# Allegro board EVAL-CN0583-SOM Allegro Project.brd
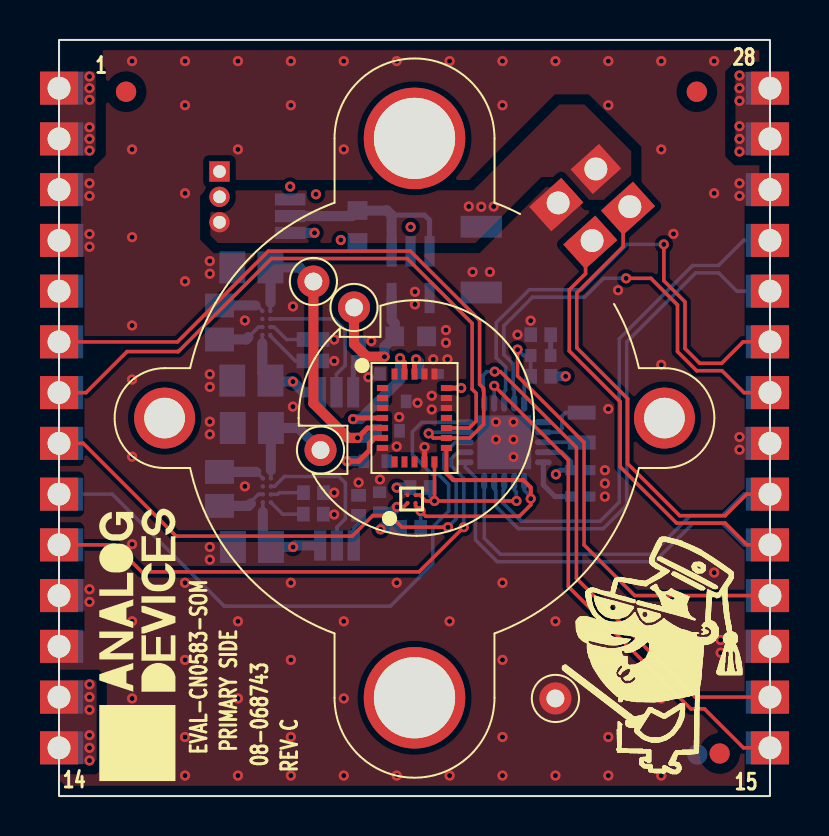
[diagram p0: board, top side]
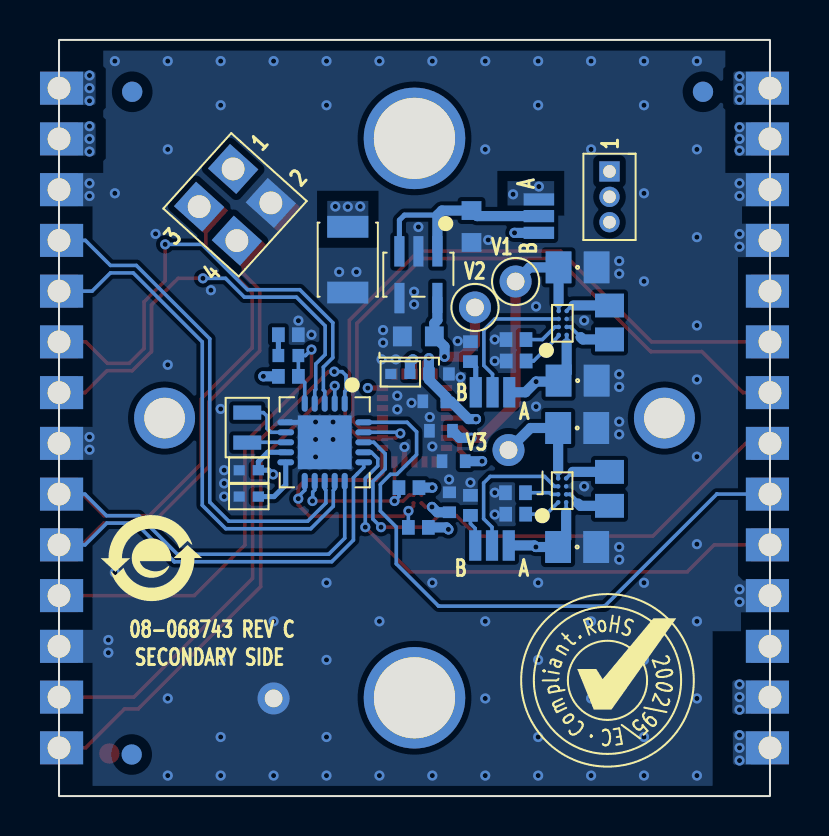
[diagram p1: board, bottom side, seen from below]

Outline 35.56 x 37.85 mm; copper layers: TOP, L2_GND, L3_VCC, BOTTOM. Coordinates in mm from the lower left corner of the outline.
Outline path: rectangle 0,0 35.56,37.85

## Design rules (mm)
constraint set DEFAULT: min track width 0.178

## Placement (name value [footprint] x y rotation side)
C1  0.1uF  [C0402]  24.09 22.05 0 bottom
C2  1uF  [C0402H22]  26.07 16.31 0 bottom
C3  1uF  [C0402H22]  26.07 14.99 0 bottom
C4  0.1uF  [C0402]  16.03 14.71 90 bottom
C5  10UF  [C0402H32]  16.79 19.76 0 bottom
C6  0.1uF  [C0402]  16.56 21.13 180 bottom
C7  10UF  [C0402H32]  16.46 18.28 0 bottom
C8  10UF  [C0402H32]  15.82 16.76 0 bottom
C9  1uF  [C0402H22]  18.49 21.13 0 bottom
C10  100uF  [C1210H106]  21.12 26.85 270 bottom
C11  22uF  [C0805H60]  9.62 20.79 180 bottom
C12  22uF  [C0805H60]  9.62 26.46 180 bottom
C13  22uF  [C0805H60]  9.65 12.47 180 bottom
C14  22uF  [C0805H60]  9.64 18.42 180 bottom
C15  2.2uF  [C0603]  14.93 28.51 270 bottom
C16  2.2uF  [C0603]  17.59 23.01 0 bottom
GND  TP_VIA  [TPC63D35]  24.83 4.89 0 top
JP1  M50-3530342  [CNTHMHDR1X3L150W83H169]  8.03 31.26 270 bottom
JP2  3PIN_SOLDER_JUMPER  [JPRSLD03]  13.88 20.21 0 bottom
JP3  3PIN_SOLDER_JUMPER  [JPRSLD03]  13.9 12.54 0 bottom
JP4  3PIN_SOLDER_JUMPER  [JPRSLD03]  11.56 29.03 270 bottom
L1  2.2UH  [L0805]  8.03 23.7 90 bottom
L2  2.2UH  [L0805]  8.03 15.38 90 bottom
NOREF  -  []  35.56 0 90 top
NOREF#2  -  [unnamed#2]  17.78 4.92 0 top
NOREF#3  -  []  0 37.85 0 top
NOREF#4  -  []  -81.28 185.29 0 top
NOREF#5  -  [unnamed#2]  3.35 35.26 0 top
NOREF#6  -  []  6.02 -64.44 0 top
NOREF#7  -  []  0 0 0 top
NOREF#8  -  []  -119.38 -141.1 0 top
NOREF#9  -  []  -119.38 -141.1 0 top
NOREF#10  -  []  5.28 18.92 0 top
NOREF#11  -  []  5.28 18.92 0 top
NOREF#12  -  []  35.56 35.43 0 top
NOREF#13  -  [unnamed#2]  30.28 18.92 0 top
NOREF#14  -  [unnamed#2]  33.04 2.13 0 top
NOREF#15  -  []  35.56 0 90 top
NOREF#16  -  []  17.78 18.92 0 top
NOREF#17  -  []  0 0 0 top
NOREF#18  -  []  35.56 37.85 180 top
NOREF#19  -  []  3.92 7.45 90 top
NOREF#20  -  [unnamed#2]  17.78 32.92 0 top
NOREF#21  -  []  0 0 0 top
NOREF#22  -  []  0 37.85 0 top
NOREF#23  -  []  -68.58 1.14 0 top
NOREF#24  -  []  -61.34 232.28 0 top
NOREF#25  -  [unnamed#2]  5.28 18.92 0 top
NOREF#26  -  [unnamed#2]  31.9 35.26 0 top
NOREF#27  -  []  0 37.85 270 top
NOREF#28  -  []  35.56 0 0 top
NOREF#29  -  []  -119.38 -141.1 0 top
NOREF#30  -  []  -119.38 -141.1 0 top
NOREF#31  -  []  260.53 309.63 0 top
NOREF#32  -  []  5.28 18.92 0 top
NOREF#33  -  [unnamed#2]  3.35 35.25 180 bottom
NOREF#34  -  [unnamed#2]  31.93 2.08 180 bottom
NOREF#35  -  []  19.5 31.16 180 bottom
NOREF#36  -  []  -17.78 5.16 180 bottom
NOREF#37  -  [unnamed#2]  31.9 35.25 180 bottom
P1  TSW-102-08-T-D  [CNSAMTEC2X2H338LD36]  26.85 31.39 312 bottom
P2-A  TSW-114-16-G-S  [CNHDR1X14H420]  0 35.43 270 top
P2-B  TSW-114-16-G-S  [CNHDR1X14H420]  35.56 35.43 270 top
R1  10K  [R0402]  24.09 21.01 180 bottom
R2  10  [R0402]  24.09 23.09 180 bottom
R3  10K  [R0402]  18.06 15.44 0 bottom
R4  10K  [R0402]  17.59 13.45 0 bottom
R5  10K  [R0402]  14.98 22.25 90 bottom
R6  324K  [R0402]  12.69 21.78 0 bottom
R7  324K  [R0402]  12.7 22.85 0 bottom
R8  10K  [R0402]  14.98 14.55 90 bottom
R9  40.2K  [R0402]  12.72 14.11 0 bottom
R10  324K  [R0402]  12.73 15.18 0 bottom
U1  MAX32660GTP+  [QFN20_4X4_PAD2_7X2_7]  22.27 17.71 0 bottom
U2  MAX31875R0TZS+T  [WLCSP4H15]  17.63 14.87 0 top
U3  ADPD188BI-ACEZ  [LGA24_A]  17.78 18.92 270 top
U4  MAX77837EWA+T  [WLP8_W81E1_1]  10.37 23.68 90 bottom
U5  MAX77837EWA+T  [WLP8_W81E1_1]  10.39 15.3 90 bottom
U6  ADP162AUJZ-1.8  [TSOT-5]  17.59 26.1 0 bottom
VDD  TP_VIA  [TPC63D35]  14.75 24.46 0 top
VLED1  TP_VIA  [TPC63D35]  12.72 25.76 0 top
VLED3  TP_VIA  [TPC63D35]  13.08 17.32 0 top
Y1  32.768KHZ  [YSML79W47H24]  26.15 18.44 270 bottom

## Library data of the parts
C1 C4 C6 = CAP: User Part Number: UPN; Tolerance: 10; alternate symbols: (C0402); part number: CAP_SM-0.1UF,16V,10,E033898,C0402; tolerance: 10
C2 C3 C9 = CAP: Tolerance: 10; User Part Number: UPN; alternate symbols: (C0402H22); part number: CAP_SM-1UF,25V,10,E033656,C0402H22; tolerance: 10
C5 C7 C8 = CAP: User Part Number: UPN; Tolerance: 20; alternate symbols: (C0402H32); part number: CAP_SM-10UF,10V,20,E057793,C0402H32; tolerance: 20
C10 = CAP: Tolerance: 20; User Part Number: UPN; alternate symbols: (C1210H106); part number: CAP_SM-100UF,10V,20,E033226,C1210H106; tolerance: 20
C11-C14 = CAP: Tolerance: 20; User Part Number: UPN; alternate symbols: (C0805H60); part number: CAP_SM-22UF,25V,20,E032575,C0805H60; tolerance: 20
C15 C16 = CAP: User Part Number: UPN; Tolerance: 10; alternate symbols: (C0603); part number: CAP_SM-2.2UF,25V,10,E031885,C0603; tolerance: 10
GND VDD VLED1 VLED3 = NCTESTPAD: Tolerance: N/A; User Part Number: UPN; alternate symbols: (TPC63D35); part number: NCTESTPAD_TH-TP_VIA,E012149,TPC63D35; tolerance: N/A
JP1 = CN3P: Tolerance: N/A; User Part Number: UPN; alternate symbols: (CNTHMHDR1X3L150W83H169); part number: CN3P_TH-M50-3530342,E055467,CNTHMHDR1X3L150W83H169; tolerance: N/A
JP2-JP4 = NC3P_JMPR: Tolerance: N/A; User Part Number: UPN; alternate symbols: (JPRSLD03); part number: NC3P_JMPR_SM-3PIN_SOLDER_JUMPER,E005606,JPRSLD03; tolerance: N/A
L1 L2 = IND: User Part Number: UPN; Tolerance: 20; alternate symbols: (L0805); part number: IND_SM-2.2UH,20,E033261,L0805; tolerance: 20
P1 = CN4P: User Part Number: UPN; Tolerance: N/A; alternate symbols: (CNSAMTEC2X2H338LD36); part number: CN4P_TH-TSW-102-08-T-D,E031363,CNSAMTEC2X2H338LD36; tolerance: N/A
P2-A P2-B = CN14P: User Part Number: UPN; Tolerance: N/A; alternate symbols: (CNHDR1X14H420); part number: CN14P_TH-TSW-114-16-G-S,E017083,CNHDR1X14H420; tolerance: N/A
R1 R3-R5 R8 = RES: User Part Number: UPN; Tolerance: 1; alternate symbols: (R0402); part number: RES_SM-10K,E003751,1/10W,1,R0402; tolerance: 1
R2 = RES: User Part Number: UPN; Tolerance: 1; alternate symbols: (R0402); part number: RES_SM-10,E003768,1/10W,1,R0402; tolerance: 1
R6 R7 R10 = RES: User Part Number: UPN; Tolerance: 1; alternate symbols: (R0402); part number: RES_SM-324K,E026129,1/10W,1,R0402; tolerance: 1
R9 = RES: User Part Number: UPN; Tolerance: 1; alternate symbols: (R0402); part number: RES_SM-40.2K,E006353,1/10W,1,R0402; tolerance: 1
U1 = ICMAX32660: User Part Number: UPN; Tolerance: N/A; alternate symbols: (QFN20_4X4_PAD2_7X2_7); part number: ICMAX32660_SM-MAX32660GTP+,E047371,QFN20_4X4_PAD2_7X2_7; tolerance: N/A
U2 = ICMAX31875: Tolerance: N/A; User Part Number: UPN; alternate symbols: (WLCSP4H15); part number: ICMAX31875_SM-MAX31875R0TZS+T,E054242,WLCSP4H15; tolerance: N/A
U3 = ADPD188BI: Tolerance: N/A; User Part Number: UPN; alternate symbols: (LGA24_A); part number: ADPD188BI_SM-ADPD188BI-ACEZ,E032759,LGA24_A; tolerance: N/A
U4 U5 = ADMAX77837: Tolerance: N/A; User Part Number: UPN; alternate symbols: (WLP8_W81E1_1); part number: ADMAX77837_SM-MAX77837EWA+T,E060730,WLP8_W81E1_1; tolerance: N/A
U6 = ADP16X_V3: User Part Number: UPN; Tolerance: N/A; alternate symbols: (TSOT-5); part number: ADP16X_V3_SM-ADP162AUJZ-1.8,E024079,TSOT-5; tolerance: N/A
Y1 = XTAL: User Part Number: UPN; Tolerance: 20ppm; alternate symbols: (YSML79W47H24); part number: XTAL_SM-32.768KHZ,E047370,YSML79W47H24; tolerance: 20ppm

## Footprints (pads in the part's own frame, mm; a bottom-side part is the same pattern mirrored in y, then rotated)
C0402
  rect 0.584x0.66 smd: 1(-0.5,0) 2(0.5,0)
C0402H22
  rect 0.559x0.508 smd: 1(-0.479,0) 2(0.479,0)
C0402H32
  rect 0.533x0.686 smd: 1(-0.577,0) 2(0.577,0)
C0603
  rect 0.94x0.991 smd: 1(-0.8,0) 2(0.8,0)
C0805H60
  rect 1.295x1.6 smd: 1(-0.953,0) 2(0.953,0)
C1210H106
  rect 1.092x2.057 smd: 1(-1.646,0) 2(1.646,0)
CNHDR1X14H420
  rect 1.651x1.905 hole 1.143: 1(0,0) 2(2.54,0) 3(5.08,0) 4(7.62,0) 5(10.16,0) 6(12.7,0) 7(15.24,0) 8(17.78,0) 9(20.32,0) 10(22.86,0) 11(25.4,0) 12(27.94,0) 13(30.48,0) 14(33.02,0)
CNSAMTEC2X2H338LD36
  rect 1.651x1.905 hole 1.143: 1(0,0)
  rect 1.651x2.159 hole 1.143: 2(0,2.54) 3(2.54,0) 4(2.54,2.54)
CNTHMHDR1X3L150W83H169
  rect 1.016x1.016 hole 0.635: 1(0,0)
  round 1.016 hole 0.635: 2(1.27,0) 3(2.54,0)
JPRSLD03
  rect 0.61x1.524 smd: 1(-0.838,0) 2(0,0) 3(0.838,0)
L0805
  rect 1.194x1.448 smd: 1(-0.85,0) 2(0.85,0)
LGA24_A
  rect 0.305x0.559 smd: 1(-1.5,-1.6) 2(-1,-1.6) 3(-0.5,-1.6) 4(0,-1.6) 5(0.5,-1.6) 6(1,-1.6) 7(1.5,-1.6) 13(1.5,1.6) 14(1,1.6) 15(0.5,1.6) 16(0,1.6) 17(-0.5,1.6) 18(-1,1.6) 19(-1.5,1.6)
  rect 0.559x0.305 smd: 8(2.2,-1) 9(2.2,-0.5) 10(2.2,0) 11(2.2,0.5) 12(2.2,1) 20(-2.2,1) 21(-2.2,0.5) 22(-2.2,0) 23(-2.2,-0.5) 24(-2.2,-1)
QFN20_4X4_PAD2_7X2_7
  oval 0.305x0.838 smd: 1(-1,-1.95) 2(-0.5,-1.95) 3(0,-1.95) 4(0.5,-1.95) 5(1,-1.95) 11(1,1.95) 12(0.5,1.95) 13(0,1.95) 14(-0.5,1.95) 15(-1,1.95)
  oval 0.838x0.305 smd: 6(1.95,-1) 7(1.95,-0.5) 8(1.95,0) 9(1.95,0.5) 10(1.95,1) 16(-1.95,1) 17(-1.95,0.5) 18(-1.95,0) 19(-1.95,-0.5) 20(-1.95,-1)
  rect 2.692x2.692 smd: PAD(0,0)
R0402
  rect 0.635x0.737 smd: 1(-0.5,0) 2(0.5,0)
TPC63D35
  round 1.6 hole 0.889: 1(0,0)
TSOT-5
  rect 0.508x1.524 smd: 1(-0.95,-1.17) 2(0,-1.17) 3(0.95,-1.17) 4(0.95,1.17) 5(-0.95,1.17)
unnamed#2
  round 5.08 hole 4.064 unplated: (0,0)
WLCSP4H15
  round 0.203 smd: A1(-0.2,-0.2) A2(-0.2,0.2) B1(0.2,-0.2) B2(0.2,0.2)
WLP8_W81E1_1
  round 0.229 smd: A1(-0.6,0.2) A2(-0.2,0.2) A3(0.2,0.2) A4(0.6,0.2) B1(-0.6,-0.2) B2(-0.2,-0.2) B3(0.2,-0.2) B4(0.6,-0.2)
YSML79W47H24
  rect 0.711x1.397 smd: 1(-0.75,0) 2(0.75,0)

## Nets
1V8_POWER: C2.1 C4.1 C5.1 C6.1 C16.1 R1.1 R3.1 R4.1 U1.9 U2.A1(VDD) U3.4 U3.19 U3.23 U6.5(VOUT) VDD.1(N1)
3V3_POWER: C8.1 C14.1 JP4.3 U3.6 U5.A4 VLED3.1(N1)
5V_POWER: C7.1 C12.1 U3.5 U4.A4 VLED1.1(N1)
GND: C2.2(N2) C3.2(N2) C4.2(N2) C5.2(N2) C6.2(N2) C7.2(N2) C8.2(N2) C9.2(N2) C10.2(N2) C11.2(N2) C12.2(N2) C13.2(N2) C14.2(N2) C15.2(N2) C16.2(N2) GND.1(N1) P1.2 P2-A.3 P2-A.4 P2-A.11 P2-A.12 P2-B.3 P2-B.8 P2-B.12 R2.2(N2) R5.2(N2) R6.2(N2) R7.2(N2) R8.2(N2) R9.2(N2) R10.2(N2) U1.6(VSS) U1.PAD U2.A2 U3.3 U3.7 U3.11 U3.17 U3.18 U3.20 U3.21 U4.B3 U5.B3 U6.2 U6.4
VBATT: JP1.1 JP4.1 P2-A.1 P2-A.2 P2-A.13 P2-A.14 P2-B.1 P2-B.2
ADPD_GPIO0: P2-A.6 U1.19 U3.14
ADPD_GPIO1: P2-A.7 U3.15
ALARM_OUT: P2-A.10 U1.17
BUTTON_IN: P2-A.9(N9) U1.20
EXT_VCC: C10.1 JP1.3(N3) P1.1
I2C_SCL: R3.2(N2) U1.12 U2.B2 U3.12
I2C_SDA: R4.2(N2) U1.11 U2.B1 U3.13
LED_OUT: P2-A.8 U1.18
RESET: C1.1 P2-B.11 R1.2(N2) U1.5
SPI_CS: P2-B.6 U1.3
SPI_MISO: P2-B.5 U1.14
SPI_MOSI: P2-B.4 U1.13
SPI_SCLK: P2-B.7 U1.4
SWDCLK: P2-B.13 U1.1
SWDIO: P2-B.14 U1.2
UART_RX: P1.3 P2-B.9(N9) U1.15
UART_TX: P1.4(N4) P2-B.10 U1.16
UNNAMED_10_ADPD188BI_I1_VREF: C9.1 U3.22(VREF)
UNNAMED_10_CAP_I73_N1: C3.1 U1.10
UNNAMED_10_CAP_I108_N2: C1.2(N2) R2.1
UNNAMED_10_ICMAX32660_I65_32KIN: U1.8 Y1.2(N2)
UNNAMED_10_ICMAX32660_I65_32KOUT: U1.7 Y1.1
UNNAMED_11_ADMAX77837_I143_EN: JP2.2(COM) U4.A3
UNNAMED_11_ADMAX77837_I143_IN: C11.1 C13.1 JP1.2 JP2.1 JP3.1 U4.B1 U5.B1
UNNAMED_11_ADMAX77837_I143_LX1: L1.1 U4.B2
UNNAMED_11_ADMAX77837_I143_LX2: L1.2(N2) U4.B4
UNNAMED_11_ADMAX77837_I143_SEL1: R6.1 U4.A1
UNNAMED_11_ADMAX77837_I143_SEL2: R7.1 U4.A2(SEL2)
UNNAMED_11_ADMAX77837_I144_EN: JP3.2(COM) U5.A3
UNNAMED_11_ADMAX77837_I144_LX1: L2.1 U5.B2
UNNAMED_11_ADMAX77837_I144_LX2: L2.2(N2) U5.B4
UNNAMED_11_ADMAX77837_I144_SEL1: R9.1 U5.A1
UNNAMED_11_ADMAX77837_I144_SEL2: R10.1 U5.A2(SEL2)
UNNAMED_11_ADP16XV3_I139_EN: C15.1 JP4.2(COM) U6.1 U6.3
UNNAMED_11_NC3PJMPR_I151_B: JP3.3 R8.1
UNNAMED_11_NC3PJMPR_I155_B: JP2.3 R5.1

Pads without a net: P2-A 5; U3 1 2 8 9 10 16 24

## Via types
v1: diameter 0.508, hole 0.254, TOP to BOTTOM, 173 vias

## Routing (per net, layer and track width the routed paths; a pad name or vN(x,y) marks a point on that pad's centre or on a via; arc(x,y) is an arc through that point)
1V8_POWER: length 21.2
  TOP w0.178: U2.A1 17.24,14.47 16.92,14.47 16.91,14.47 v1(16.91,14.47)
  TOP w0.254: U3.23 17.28,21.69 v1(17.06,21.92) ; U3.4 14.76,18.92 v1(14.7,18.87) ; v1(20.12,20.42) U3.19
  TOP w0.508: VDD.1 14.75,22.63 15.39,21.99 v1(16.28,21.99)
  BOTTOM w0.254: U1.9 25.12,17.21 25.59,16.74 C2.1 25.06,16.31 v1(24.85,16.1)
  BOTTOM w0.508: v1(14.7,18.87) 15.08,18.87 15.97,19.76 C5.1 16.21,19.99 17.06,20.84 C6.1 v1(17.06,21.92) ; R3.1 v1(16.89,15.44) ; R4.1 16.18,13.45 v1(16.08,13.35) ; C4.1 16.64,14.2 v1(16.91,14.47) ; v1(16.28,21.99) 16.28,22.5 C16.1 16.79,23.67 16.64,23.82 U6.5 ; R1.1 v1(25.34,21.01)
3V3_POWER: length 10
  TOP w0.254: v1(14.4,16.76) 14.98,16.76 15.52,17.3 15.52,17.65 15.79,17.92 U3.6
  BOTTOM w0.178: 10.59,16.31 U5.A4
  BOTTOM w0.508: C8.1 v1(14.4,16.76) ; JP4.3 v1(12.78,28.19) ; 10.59,16.31 C14.1 11.98,18.42 VLED3.1
5V_POWER: length 16.2
  TOP w0.254: v1(14.93,17.93) 15.43,18.42 U3.5
  TOP w0.508: v1(14.93,17.93) 14.45,17.93 12.72,19.66 VLED1.1
  BOTTOM w0.178: U4.A4 10.57,24.69 10.58,24.69
  BOTTOM w0.508: C7.1 15.52,17.93 v1(14.93,17.93) ; VLED1.1 12.02,26.46 C12.1 10.58,24.69
GND: length 2.3
  TOP w0.254: U3.11 v1(18.28,17.47) 18.28,17.49
  BOTTOM w0.254: U1.6 22.74,18.71 v1(22.73,18.72)
  vias: v1(1.52,30.67) v1(1.52,30.04) v1(1.52,28.13) v1(1.52,27.5) v1(1.52,10.35) v1(1.52,9.72) v1(3.66,36.79) v1(3.66,32.37) v1(3.66,27.97) v1(3.66,23.55) v1(3.66,20.85) v1(3.66,16.99) v1(3.66,12.61) v1(3.66,8.75) v1(3.66,4.89) v1(3.66,1.02) v1(6.3,36.79) v1(6.3,34.58) v1(6.3,30.17) v1(6.3,25.76) v1(6.3,10.68) v1(6.3,6.82) v1(6.3,2.96) v1(6.3,1.02) v1(7.54,26.78) v1(7.54,26.15) v1(7.54,21.11) v1(7.54,20.48) v1(7.54,18.74) v1(7.54,18.1) v1(7.54,12.47) v1(7.54,11.83) v1(8.95,36.79) v1(8.95,32.37) v1(8.95,8.75) v1(8.95,4.89) v1(8.95,1.02) v1(9.29,23.8) v1(9.29,15.5) v1(11.6,36.79) v1(11.6,34.58) v1(11.6,10.68) v1(11.6,6.82) v1(11.6,2.96) v1(11.6,1.02) v1(11.7,24.51) v1(11.7,19.49) v1(13.76,22.85) v1(13.76,21.78) v1(13.76,15.19) v1(13.76,14.09) v1(14.09,27.83) v1(14.24,36.79) v1(14.24,32.37) v1(14.24,8.75) v1(14.24,4.89) v1(14.24,1.02) v1(14.98,15.69) v1(15.48,20.96) v1(15.62,22.77) v1(16.05,15.85) v1(16.89,36.79) v1(16.89,17.5) v1(16.89,10.68) v1(16.89,1.02) v1(17.02,18.97) v1(17.59,28.48) v1(17.8,25.24) v1(17.8,24.61) v1(17.93,19.68) v1(18.72,21.86) v1(18.64,20.04) v1(18.64,19.35) v1(19.35,23.33) v1(19.35,22.69) v1(19.43,21.86) v1(19.54,36.79) v1(19.54,8.75) v1(19.54,1.02) v1(20.69,26.23) v1(21.55,26.23) v1(21.85,18.72) v1(21.85,17.85) v1(22.18,36.79) v1(22.18,34.58) v1(22.18,10.68) v1(22.18,6.82) v1(22.18,2.96) v1(22.18,1.02) v1(22.73,17.85) v1(22.73,16.98) v1(22.93,23.09) v1(23.59,23.8) v1(24.83,36.79) v1(24.83,8.75) v1(24.83,1.02) v1(27.3,16.31) v1(27.3,15.65) v1(27.3,14.99) v1(27.48,36.79) v1(27.48,34.58) v1(27.48,19.38) v1(27.48,6.82) v1(27.48,2.96) v1(27.48,1.02) v1(27.96,25.32) v1(30.12,36.79) v1(30.12,32.37) v1(30.12,21.59) v1(30.12,4.89) v1(30.12,1.02) v1(30.73,28.14) v1(32.77,36.79) v1(32.77,30.17) v1(32.77,11.18) v1(33.09,7.81) v1(33.09,7.18) v1(34.04,30.67) v1(34.04,30.04) v1(34.04,17.97) v1(34.04,17.34)
VBATT: length 0.9
  BOTTOM w0.203: P2-A.14 0.45,2.41 ; P2-A.13 0.45,4.95
  vias: v1(1.52,36.02) v1(1.52,35.43) v1(1.52,34.85) v1(1.52,33.48) v1(1.52,32.89) v1(1.52,32.31) v1(1.52,5.59) v1(1.52,4.95) v1(1.52,4.32) v1(1.52,3.05) v1(1.52,2.41) v1(1.52,1.78) v1(11.56,30.51) v1(12.85,30.12) v1(34.04,36.07) v1(34.04,35.43) v1(34.04,34.8) v1(34.04,33.53) v1(34.04,32.89) v1(34.04,32.26)
ADPD_GPIO0: length 34.6
  TOP w0.178: P2-A.6 5.93,22.73 10.47,27.28 17.57,27.28 21.04,23.81 21.04,20.61 21.24,20.4 21.24,18.62 20.55,17.92 U3.14 18.72,17.92 v1(18.49,18.15)
  BOTTOM w0.178: U1.19 18.54,18.21 v1(18.49,18.15)
ADPD_GPIO1: length 31.4
  TOP w0.178: U3.15 20.52,18.42 20.87,18.77 20.87,20.16 20.66,20.36 20.66,23.66 17.42,26.9 10.62,26.9 5.99,22.27 5.98,22.26 5.97,22.25 5.95,22.25 5.94,22.25 3.4,22.25 1.35,20.19 P2-A.7
ALARM_OUT: length 26.3
  TOP w0.178: P2-A.10 2.79,12.57 4.14,11.22 18.01,11.22 v1(20.24,13.46)
  BOTTOM w0.178: U1.17 19.94,17.21 19.62,16.89 19.62,16.53 20.24,15.9 v1(20.24,13.46)
BUTTON_IN: length 32.6
  BOTTOM w0.178: U1.20 18.15,18.71 17.68,18.23 17.68,17.09 18.66,16.1 18.98,16.1 19.49,15.6 19.49,14.26 18.69,13.47 18.69,11.62 16.59,9.53 16.58,9.52 16.57,9.51 16.56,9.51 16.54,9.51 8.29,9.51 8.28,9.51 8.27,9.51 8.26,9.52 8.25,9.52 8.24,9.53 2.67,15.1 2.66,15.11 2.65,15.11 P2-A.9
EXT_VCC:
  vias: v1(20.5,29.51) v1(21.12,29.5) v1(21.74,29.51)
I2C_SCL: length 8.9
  TOP w0.178: v1(22.88,14.77) v1(18.78,14.77) ; v1(18.78,14.77) U3.12 ; v1(18.78,14.77) 18.35,14.77 18.05,15.07 U2.B2
  BOTTOM w0.178: v1(18.78,14.77) 18.56,14.99 R3.2 ; v1(22.88,14.77) 22.88,14.91 22.87,14.92 22.87,15.22 22.77,15.32 U1.12
I2C_SDA: length 14.8
  TOP w0.178: v1(23.59,14.89) 23.59,14.58 23.02,14 18.35,14 v1(18.08,14.27) 17.83,14.52 U2.B1
  TOP w0.203: v1(23.59,14.89) 23.59,15.44 23.22,15.82 19.71,15.82 19.38,16.15 U3.13
  BOTTOM w0.178: v1(18.08,14.27) 18.09,14.27 R4.2 ; U1.11 23.27,15.31 23.59,14.98 v1(23.59,14.89)
LED_OUT: length 27.5
  TOP w0.178: P2-A.8 1.21,17.65 5.85,13.01 14.66,13.01 15.69,14.04 16.57,14.04 17.15,13.46 v1(19.45,13.46)
  BOTTOM w0.178: v1(19.45,13.46) 19.86,13.86 19.86,15.75 19.24,16.37 19.24,17.13 19.82,17.71 U1.18
RESET: length 24.8
  TOP w0.178: P2-B.11 28.8,10.03 26.26,12.57 26.26,17.7 22.93,21.03 v1(22.93,22.35)
  BOTTOM w0.178: U1.5 23.27,20.69 R1.2 C1.1 23.23,22.05 v1(22.93,22.35)
SPI_CS: length 24.9
  TOP w0.178: v1(30.25,27.61) 30.25,25.79 31.31,24.74 31.31,22.4 32.05,21.66 33.14,21.66 34.22,22.73 P2-B.6
  BOTTOM w0.178: v1(30.25,27.61) 28.4,27.61 26.13,25.35 23.52,25.35 21.87,23.69 21.87,21.94 22.34,21.47 22.34,20.33 22.27,20.26 U1.3
SPI_MISO: length 25.9
  BOTTOM w0.178: U1.14 21.77,15.37 21.84,15.3 21.84,14.51 22.97,13.38 27.22,13.38 28.39,14.56 28.39,22.73 31.85,26.19 32.99,26.19 33.9,25.27 P2-B.5
SPI_MOSI: length 25.5
  BOTTOM w0.178: U1.13 22.27,15.37 22.21,15.32 22.21,14.66 23.12,13.76 27.07,13.76 28.02,14.71 28.02,22.89 31.69,26.56 32.99,26.56 34.24,27.81 P2-B.4
SPI_SCLK: length 22.1
  TOP w0.178: P2-B.7 34.26,20.19 33.16,21.29 31.89,21.29 30.93,22.25 30.93,24.58 29.6,25.91 v1(28.36,25.91)
  BOTTOM w0.178: U1.4 22.77,20.3 22.72,20.35 22.72,21.63 22.25,22.1 22.25,23.54 23.68,24.97 26.29,24.97 27.23,25.91 v1(28.36,25.91)
SWDCLK: length 26.4
  TOP w0.178: v1(21.79,21.24) 22.08,21.24 25.88,17.45 25.88,10.89 31.82,4.95 P2-B.13
  BOTTOM w0.178: v1(21.79,21.24) 21.4,21.24 21.21,21.05 21.21,20.31 21.27,20.25 U1.1
SWDIO: length 25.9
  TOP w0.178: P2-B.14 34.23,2.41 32.28,4.36 31.6,4.36 25.47,10.49 25.47,16.83 v1(21.77,20.53)
  BOTTOM w0.178: v1(21.77,20.53) U1.2
UART_RX: length 42.4
  TOP w0.178: P2-B.9 34.39,15.11 33.31,14.03 31.04,14.03 28.44,16.64 28.44,19.89 25.9,22.43 25.9,25.18 28.22,27.5 28.22,29.17 P1.3
  BOTTOM w0.178: P2-B.9 34.27,15.11 33.19,14.03 31.57,14.03 29.64,12.1 22.07,12.1 21.27,12.91 U1.15
UART_TX: length 42.5
  TOP w0.178: P2-B.10 34.41,12.57 33.32,13.66 30.89,13.66 28.07,16.48 28.07,19.73 25.52,22.28 25.52,25.34 26.34,26.15 26.34,27.48 P1.4
  BOTTOM w0.178: U1.16 20.32,16.45 20.63,16.14 20.64,16.13 20.83,15.94 20.83,12.82 21.92,11.73 29.77,11.73 29.79,11.73 29.79,11.73 29.8,11.74 30.12,12.06 30.12,12.06 31.72,13.66 33.17,13.66 34.26,12.57 P2-B.10
UNNAMED_10_ADPD188BI_I1_VREF: length 1.6
  TOP w0.254: v1(17.86,21.86) 17.78,21.78 U3.22
  BOTTOM w0.508: C9.1 18.01,21.71 v1(17.86,21.86)
UNNAMED_10_CAP_I73_N1: length 2.7
  BOTTOM w0.254: U1.10 24.22,15.57 24.81,14.99 C3.1
UNNAMED_10_CAP_I108_N2: length 1
  BOTTOM w0.254: R2.1 C1.2
UNNAMED_10_ICMAX32660_I65_32KIN: length 1.9
  BOTTOM w0.178: U1.8 26.13,17.71 Y1.2
UNNAMED_10_ICMAX32660_I65_32KOUT: length 2.7
  BOTTOM w0.178: Y1.1 25.33,19.19 25.15,19.01 25.15,18.4 24.96,18.21 U1.7
UNNAMED_11_ADMAX77837_I143_EN: length 7.3
  BOTTOM w0.178: U4.A3 13.76,23.88 14.31,23.32 14.31,21.55 13.88,21.12 JP2.2
UNNAMED_11_ADMAX77837_I143_IN: length 10.1
  BOTTOM w0.178: 10.17,22.67 U4.B1 ; 10.19,14.21 U5.B1
  BOTTOM w0.508: 10.17,22.67 10.17,21.2 C11.1 10.62,20.74 v1(11.7,20.74) 12.23,20.21 JP2.1 ; 10.19,14.21 10.19,12.87 C13.1 v1(11.71,12.47) 11.78,12.54 JP3.1
UNNAMED_11_ADMAX77837_I143_LX1: length 2.4
  BOTTOM w0.178: 9.47,22.96 9.98,23.48 U4.B2
  BOTTOM w0.508: 9.47,22.96 9.36,22.85 L1.1
UNNAMED_11_ADMAX77837_I143_LX2: length 2.3
  BOTTOM w0.178: 9.83,24.55 9.93,24.55 U4.B4
  BOTTOM w0.508: 9.83,24.55 L1.2
UNNAMED_11_ADMAX77837_I143_SEL1: length 2.2
  BOTTOM w0.178: R6.1 11.82,21.78 10.57,23.03 U4.A1
UNNAMED_11_ADMAX77837_I143_SEL2: length 1.9
  BOTTOM w0.178: R7.1 11.38,22.85 10.75,23.48 U4.A2
UNNAMED_11_ADMAX77837_I144_EN: length 7.4
  BOTTOM w0.178: JP3.2 13.9,13.46 14.32,13.88 14.32,15.67 14,16 11.28,16 10.78,15.5 U5.A3
UNNAMED_11_ADMAX77837_I144_LX1: length 2.5
  BOTTOM w0.178: U5.B2 10.03,15.1 10.03,15.1 9.97,15.1 9.6,14.73 9.6,14.64
  BOTTOM w0.508: 9.6,14.64 9.48,14.53 L2.1
UNNAMED_11_ADMAX77837_I144_LX2: length 2.3
  BOTTOM w0.178: 9.87,16.23 U5.B4
  BOTTOM w0.508: L2.2 9.87,16.23
UNNAMED_11_ADMAX77837_I144_SEL1: length 1.9
  BOTTOM w0.178: R9.1 11.19,14.11 U5.A1
UNNAMED_11_ADMAX77837_I144_SEL2: length 1.7
  BOTTOM w0.178: U5.A2 10.94,15.1 11.02,15.18 R10.1
UNNAMED_11_ADP16XV3_I139_EN: length 10.7
  BOTTOM w0.254: U6.3 18.54,28.82 18.28,29.08 16.64,29.08
  BOTTOM w0.508: JP4.2 14.65,29.03 C15.1 16.41,29.31 16.64,29.08 U6.1
UNNAMED_11_NC3PJMPR_I151_B: length 1.6
  BOTTOM w0.178: JP3.3 14.74,13.39 14.98,13.64 R8.1
UNNAMED_11_NC3PJMPR_I155_B: length 1.6
  BOTTOM w0.254: R5.1 14.98,21.74 14.72,21.47 JP2.3

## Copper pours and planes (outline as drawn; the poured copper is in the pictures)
1V8_POWER on L3_VCC: 21.59,31.47 28.85,31.47 29.34,30.98 29.33,12.3 28.83,11.81 12.52,11.81 12.52,14.04 15.39,14.04 15.49,14.06 15.57,14.12 16.03,14.6 16.08,14.68 16.1,14.78 16.1,18.79 15.03,18.79 15.03,18.79 15.03,21.43 16.08,21.43 16.08,29.93 16.82,30.68 20.7,30.68 20.8,30.7 20.88,30.76
3V3_POWER on L3_VCC: 11.17,29.33 15.57,29.33 15.57,21.08 14.45,19.96 14.45,17.78 15.59,17.77 15.59,14.88 15.28,14.55 12.37,14.55 11.4,15.52 11.4,18.64 12.37,19.6 12.42,19.69 12.44,19.78 12.44,21.11 11.17,22.38
GND on TOP: 1.68,37.34 10.97,37.34 10.97,37.34 35.03,37.34 35.03,31.19 35.66,31.19 35.66,29.51 35.56,29.51 35.56,6.12 35.51,6.07 35.03,6.07 35.03,0.51 0.23,0.51 0.23,0.58 0,0.81 0,8.25 1.27,8.25 1.27,9.27 0,9.27 0,29.54 0.05,29.54 0,29.59 0,31.14 0.03,31.17 0.23,31.17 0.23,37.34 1.68,37.34 ; 1 cut-out
GND on BOTTOM: 2.23,37.31 33.35,37.31 33.35,31.19 35.53,31.19 35.56,31.17 35.56,29.51 33.88,29.51 33.88,18.48 35.56,18.48 35.56,16.83 33.88,16.83 33.88,8.32 35.56,8.32 35.56,6.67 33.88,6.67 33.88,0.51 2.87,0.51 2.87,8.25 1.22,8.25 1.22,6.73 0.07,6.73 0.07,10.66 0.2,10.79 1.34,10.79 1.6,11.05 1.6,26.97 0,26.97 0,31.19 2.23,31.19
GND on L2_GND: 1.27,37.34 34.24,37.34 34.24,30.96 35.64,30.96 35.64,29.74 34.29,29.74 34.29,18.23 35.64,18.23 35.64,17.06 34.29,17.06 34.29,8.32 35.56,8.32 35.56,6.68 34.29,6.68 34.29,3.23 34.26,3.23 34.26,1.7 34.29,1.7 34.29,0.51 1.27,0.51 1.27,6.68 0,6.68 0,8.32 1.27,8.32 1.27,9.22 0,9.22 0,10.86 1.27,10.86 1.27,29.77 -0.13,29.77 -0.13,30.94 1.27,30.94
VBATT on TOP: -0.03,36.27 1.73,36.27 1.83,36.17 1.83,32.28 1.6,32.05 0,32.05 -0.03,32.08
VBATT on TOP: 0.03,5.82 1.78,5.82 1.88,5.71 1.88,1.83 1.65,1.6 0.05,1.6 0.03,1.63
VBATT on TOP: 35.56,36.25 35.56,32.2 35.43,32.08 33.99,32.08 33.83,32.23 33.83,36.07 34.01,36.25
VBATT on BOTTOM: 10.8,29.56 10.8,30.78 13.13,30.78 13.13,29.56
VBATT on BOTTOM: 35.58,33.73 35.58,32.05 33.8,32.05 33.73,32.13 33.73,33.65 33.8,33.73
VBATT on BOTTOM: 35.58,36.27 35.58,34.59 33.8,34.59 33.73,34.67 33.73,36.19 33.8,36.27
VBATT on BOTTOM: 0.03,5.79 0.03,4.11 1.81,4.11 1.88,4.19 1.88,5.71 1.81,5.79
VBATT on BOTTOM: -0.02,33.73 -0.02,32.05 1.76,32.05 1.83,32.13 1.83,33.65 1.76,33.73
VBATT on BOTTOM: 0,3.25 0,1.57 1.78,1.57 1.86,1.65 1.86,3.17 1.78,3.25
VBATT on BOTTOM: -0.02,36.27 -0.02,34.59 1.76,34.59 1.83,34.67 1.83,36.19 1.76,36.27
VBATT on L3_VCC: 1.22,37.34 35.66,37.34 35.66,0.51 1.22,0.51 ; 2 cut-outs
EXT_VCC on TOP: 7.57,28.06 7.57,29.84 8.05,30.32 20.72,30.32 25.02,34.62 26.29,34.62 28.62,32.28 28.62,31.09 27.38,29.84 26.49,29.84 25.35,30.98 24.13,30.98 20.83,27.68 7.95,27.68
EXT_VCC on BOTTOM: 20.09,27.95 20.09,29.79 22.15,29.79 22.15,27.95
UNNAMED_11_ADMAX77837_I143_IN on L3_VCC: 7.44,30.5 10.66,30.5 10.66,22.17 11.94,20.9 11.94,19.89 10.97,18.92 10.91,18.84 10.89,18.74 10.89,15.41 10.91,15.32 10.97,15.23 12.01,14.19 12.01,11.81 8.28,11.81 7.44,12.65

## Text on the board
Ref Des/Silkscreen Bottom: V1 | V3 | V2 | 08-068743 REV C | SECONDARY SIDE
User.Comments: 5.    BOARDS TO BE SHIPPED SINGULATED AFTER ASSEMBLY PROCESS. | 6.    ASSEMBLY VENDOR SHOULD INSTALL ACCUMOLD 28800X CHAMBER. | 7.    ASSEMBLY VENDOR SHOULD INSTALL RIVETS (M045128). | SMOOTHEN EDGES AND FREE FROM BURRS AFTER DEPANELIZATION PROCESS.
Ref Des/Silkscreen Top: 14 | 1 | 28 | 15 | EVAL-CN0583-SOM | PRIMARY SIDE | 08-068743 | REV C
PAGE_OUTLINE: B | C | ECR-111942 | ECR-115064 | 24MAR23 | 28JUL23 | A. UY | CUSTOMER EVALUATION Z
DIMENSION: " " | (REF) | CASTELLATED AT 28 PLACES | DIA MAX | SEE NOTE 15
User.12: 1 | 2 | 3 | ASSEMBLY NOTES 2 | 8.    APPLY SOLDER BLOB ON JP2, JP3 AND JP4 PIN 1 AND 2 | 9.    SHUNT M028265 TO BE INSTALLED ON JP1 PIN 1 AND 2.
User.15: 15.    NOTE THE 28 CASTELLATED VIA HOLES AROUND THE BOARD EDGES. | 16.    BOARDS TO BE SHIPPED IN ARRAY AND KEEP INTACT. | PANEL TO BE SUBJECTED TO CUSTOMER'S APPROVAL. | PANELED SOLDER PASTE STENCIL SHOULD BE SENT TO THE CUSTOMER. | CASTELLATED PAD DEFINITION | TOP - RECTANGLE .065 X .075 INCH | INTERNAL (LAYER 2 & 3) - CIRCLE .065 INCH | BOTTOM - RECTANGLE .065 X .085 INCH | .100 INCH
User.24: L2 GND | 08-      -07
User.25: L3 VCC | 08-      -08
User.45: FIGURE | SIZE | 10.0 | 25.0 | 35.0 | 45.0 | 80.0 | 160.0 | PLATED | NON-PLATED | DRILL CHART: TOP to BOTTOM | ALL UNITS ARE IN MILS | QTY | 173 | 3 | 4 | 32 | 2 | TOLERANCE/NOTES
